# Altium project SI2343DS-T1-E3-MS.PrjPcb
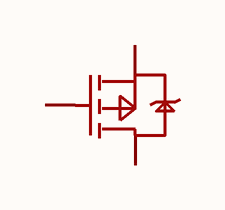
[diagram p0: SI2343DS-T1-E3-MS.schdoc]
1 sheet, 1 parts. Net scope: global (net labels, ports and power ports of the same name join across sheets).

## Sheet SI2343DS-T1-E3-MS.schdoc
size 127 x 101 mm

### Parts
Q?  si2343ds-t1-e3-ms  [SOT-23-3_L2.9-W1.3-P1.90-LS2.4-BR]  (value not drawn)

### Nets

Not connected (* = marked no-connect by the designer): Q? 1(G) 2(S) 3(D)

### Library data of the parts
Q? = si2343ds-t1-e3-ms: 数量:1个P沟道;漏源电压(Vdss):30V;连续漏极电流(Id):4A;导通电阻(RDS(on)):45mΩ@10V;耗散功率(Pd):1.56W;阈值电压(Vgs(th)):1.6V;; Manufacturer: MSKSEMI(美森科); AddInBom: yes; ModelId: c62791f0466c4ae2a892c056b845b0ca; ModelName: SOT-23-3P_L2.9-W1.3-H1.0-LS2.4-P0.95; ModelTransform: 98.425,114.173,0,180,0,0,0.0005,-0.0005,0; Number: 1个P沟道; Drain to Source Voltage: 30V; Current - Continuous Drain(Id): 4A; Pd - Power Dissipation: 1.56W; Gate Threshold Voltage (Vgs(th)): 1.6V; Gate Charge(Qg): 5.1nC@4.5V; Input Capacitance(Ciss): 560pF; Reverse Transfer Capacitance (Crss@Vds): 40pF; Type: P沟道; Output Capacitance(Coss): 55pF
